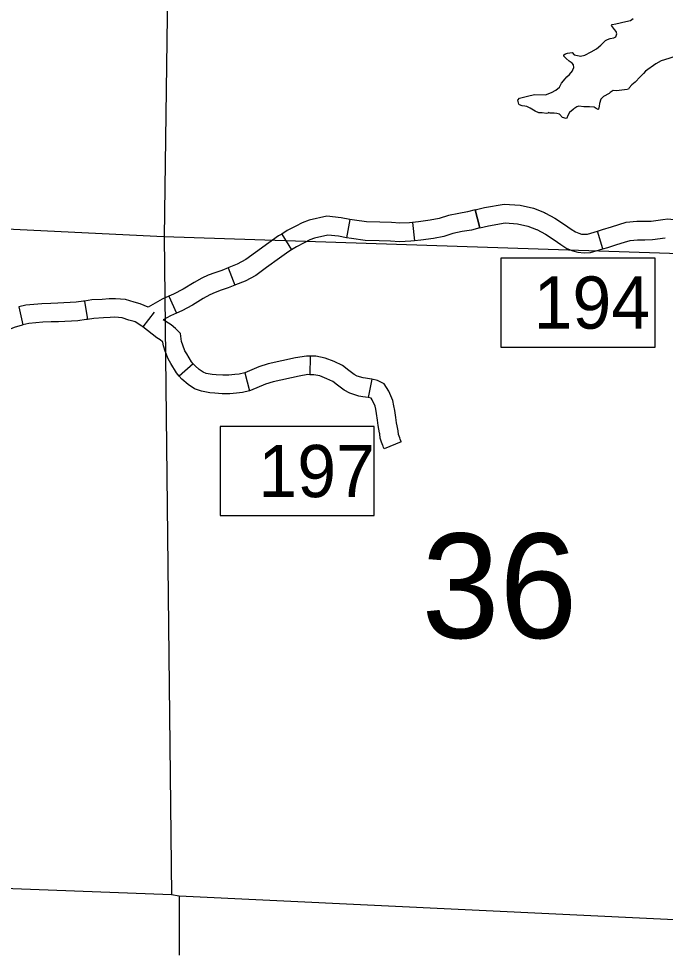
# Model space of a CAD drawing. Extents: x -492261 to -432772, y 1441225 to 1452922.
# Drawn here: x -463526 to -463376.9, y 1450874.7 to 1451090.8 of the extents above; entities that cross this region are included whole.
import ezdxf

# ---------------------------------------------------------------- set-up
doc = ezdxf.new("R2010")
doc.units = 0
doc.layers.add('Default', color=7, linetype='Continuous')

msp = doc.modelspace()

# ---------------------------------------------------------------- linework, layer by layer
at = {"layer": 'Default'}
for p, q in [((-463419.67, 1451042.53), (-463420.73, 1451046.69)), ((-463420.73, 1451046.69), (-463419.67, 1451042.53)), ((-463449.62, 1451044.5), (-463450.39, 1451040.28)), ((-463435.21, 1451043.81), (-463434.74, 1451039.55)), ((-463465.35, 1451041.12), (-463463.1, 1451037.47)), ((-463391.27, 1451037.7), (-463392.54, 1451041.79)), ((-463477.72, 1451033.31), (-463476.17, 1451029.31)), ((-463510.88, 1451025.65), (-463510.19, 1451021.42)), ((-463491.39, 1451026.79), (-463489.65, 1451022.87)), ((-463526.02, 1451024.35), (-463525.05, 1451020.18)), ((-463494.76, 1451023.07), (-463497.39, 1451019.69)), ((-463458.76, 1451012.95), (-463458.87, 1451008.67)), ((-463485.75, 1451011.15), (-463488.99, 1451008.35)), ((-463473.88, 1451009.12), (-463472.81, 1451004.97)), ((-463444.55, 1451007.63), (-463445.45, 1451003.44)), ((-463437.77, 1450993.16), (-463441.74, 1450991.55))]:
    msp.add_line(p, q, dxfattribs=at)
for points in [[(-463491.53, 1451108.34), (-463492.51, 1451040.46), (-463490.8, 1450888.59)], [(-463383.83, 1451076.16), (-463384.57, 1451075.58), (-463385.19, 1451074.88), (-463385.36, 1451074.59), (-463385.7, 1451074.48), (-463388.15, 1451074.21), (-463388.9, 1451074.26), (-463389.58, 1451073.8), (-463389.86, 1451073.56), (-463391.11, 1451072.86), (-463391.78, 1451072.28), (-463392.06, 1451071.25), (-463392.11, 1451070.62), (-463392.27, 1451069.99), (-463392.38, 1451069.87), (-463392.84, 1451070.09), (-463393.3, 1451070.43), (-463394.39, 1451070.48), (-463394.73, 1451070.47), (-463395.65, 1451070.46), (-463396.85, 1451070.62), (-463397.3, 1451070.5), (-463397.98, 1451070.03), (-463398.15, 1451069.91), (-463398.94, 1451069.16), (-463399.34, 1451068.52), (-463399.56, 1451067.84), (-463399.78, 1451067.78), (-463400.59, 1451068.05), (-463401.28, 1451068.79), (-463401.91, 1451068.95), (-463402.48, 1451069.06), (-463403.46, 1451069.04), (-463403.91, 1451069.15), (-463403.91, 1451069.04), (-463404.25, 1451068.92), (-463405.28, 1451069.08), (-463406.03, 1451069.13), (-463406.89, 1451069.51), (-463408.04, 1451070.19), (-463408.79, 1451070.58), (-463409.3, 1451070.63), (-463409.88, 1451070.73), (-463410.51, 1451070.96), (-463410.68, 1451071.12), (-463410.87, 1451072.04), (-463410.53, 1451072.5), (-463408.02, 1451073.1), (-463407, 1451073.34), (-463404.54, 1451073.26), (-463403.12, 1451073.79), (-463402.09, 1451074.32), (-463401.3, 1451075.02), (-463400.8, 1451075.94), (-463400.01, 1451076.92), (-463399.56, 1451077.39), (-463399, 1451077.96), (-463398.32, 1451078.83), (-463398.21, 1451079), (-463397.99, 1451079.58), (-463398.06, 1451080.15), (-463398.35, 1451080.55), (-463399.04, 1451081.05), (-463399.73, 1451081.62), (-463400.31, 1451082.18), (-463400.31, 1451082.52), (-463399.86, 1451082.76), (-463399.4, 1451082.88), (-463398.38, 1451083.01), (-463397.91, 1451082.5), (-463396.77, 1451082.28), (-463396.42, 1451082.17), (-463395.46, 1451082.41), (-463393.98, 1451083.18), (-463392.73, 1451083.88), (-463391.71, 1451084.75), (-463390.64, 1451085.79), (-463390.19, 1451086.03), (-463389.62, 1451086.26), (-463388.76, 1451086.39), (-463388.25, 1451086.68), (-463388.03, 1451087.31), (-463388.21, 1451087.88), (-463388.56, 1451088.33), (-463389.32, 1451089.24), (-463389.15, 1451089.53), (-463388.29, 1451089.65), (-463385.96, 1451090.2), (-463384.93, 1451090.38), (-463384.25, 1451090.85)], [(-463368.01, 1451076.36), (-463368.01, 1451076.02), (-463368.35, 1451075.84), (-463369.03, 1451075.77), (-463369.55, 1451075.88), (-463370.24, 1451076.39), (-463370.42, 1451076.84), (-463370.71, 1451077.81), (-463370.9, 1451079.01), (-463371.2, 1451080.38), (-463371.73, 1451081.12), (-463372.31, 1451081.74), (-463373.11, 1451082.13), (-463374.48, 1451082.22), (-463376.08, 1451081.63), (-463377.84, 1451081.09), (-463379.03, 1451080.39), (-463381.41, 1451078.76), (-463381.92, 1451078.18), (-463382.65, 1451077.43), (-463383.83, 1451076.16)], [(-463345.55, 1451035.65), (-463492.57, 1451040.51), (-463644.02, 1451047.89), (-463656.98, 1451048.34)], [(-463420.73, 1451046.69), (-463418.57, 1451047.23), (-463414.08, 1451048), (-463410.35, 1451047.77), (-463407.27, 1451047.08), (-463404.77, 1451046.07), (-463404.5, 1451045.93)], [(-463449.62, 1451044.5), (-463451.64, 1451044.87), (-463454.93, 1451045.24), (-463459.03, 1451044.31), (-463460.64, 1451043.69), (-463462.12, 1451042.94), (-463464.07, 1451041.91), (-463465.35, 1451041.12)], [(-463420.73, 1451046.69), (-463422.5, 1451046.24), (-463424.51, 1451045.89), (-463426.92, 1451045.39), (-463429.01, 1451044.75), (-463431.08, 1451044.37), (-463433.79, 1451043.96), (-463435.21, 1451043.81)], [(-463404.5, 1451045.93), (-463402.36, 1451044.79), (-463400.13, 1451043.36), (-463398.58, 1451042.27), (-463397.59, 1451041.63), (-463396.85, 1451041.34), (-463396.21, 1451041.14), (-463395.5, 1451041.07), (-463394.83, 1451041.11), (-463393.25, 1451041.57), (-463392.54, 1451041.79)], [(-463435.21, 1451043.81), (-463435.89, 1451043.73), (-463438.11, 1451043.66), (-463440.04, 1451043.76), (-463442.75, 1451043.86), (-463445.79, 1451043.95), (-463448.6, 1451044.31), (-463449.62, 1451044.5)], [(-463419.67, 1451042.53), (-463417.68, 1451043.04), (-463413.85, 1451043.69), (-463410.95, 1451043.51), (-463408.55, 1451042.98), (-463406.58, 1451042.18), (-463406.52, 1451042.15)], [(-463392.54, 1451041.79), (-463391.39, 1451042.15), (-463389.28, 1451042.79), (-463387.58, 1451043.31), (-463385.91, 1451043.84), (-463383.44, 1451044.12), (-463381.65, 1451044.08), (-463380.16, 1451044.14), (-463377.44, 1451044.49)], [(-463377.44, 1451044.49), (-463376.3, 1451044.64), (-463371.96, 1451044.17), (-463364.65, 1451043.13), (-463361.98, 1451042.87)], [(-463465.35, 1451041.12), (-463466.07, 1451040.68), (-463468.35, 1451039.07), (-463471.39, 1451036.86), (-463473.6, 1451035.22), (-463475.63, 1451034.14), (-463477.56, 1451033.37), (-463477.72, 1451033.31)], [(-463450.39, 1451040.28), (-463452.27, 1451040.63), (-463454.69, 1451040.9), (-463457.77, 1451040.2), (-463458.89, 1451039.77), (-463460.15, 1451039.13), (-463461.95, 1451038.18), (-463463.1, 1451037.47)], [(-463419.67, 1451042.53), (-463421.61, 1451042.04), (-463423.71, 1451041.68), (-463425.86, 1451041.23), (-463427.99, 1451040.58), (-463430.37, 1451040.14), (-463433.24, 1451039.71), (-463434.74, 1451039.55)], [(-463406.52, 1451042.15), (-463404.53, 1451041.09), (-463402.52, 1451039.8), (-463400.98, 1451038.73), (-463399.56, 1451037.79), (-463398.24, 1451037.29), (-463397.06, 1451036.92), (-463395.59, 1451036.78), (-463394.1, 1451036.86), (-463392.02, 1451037.46), (-463391.27, 1451037.7)], [(-463434.74, 1451039.55), (-463435.59, 1451039.45), (-463438.16, 1451039.37), (-463440.23, 1451039.48), (-463442.89, 1451039.58), (-463446.13, 1451039.67), (-463449.26, 1451040.08), (-463450.39, 1451040.28)], [(-463391.27, 1451037.7), (-463390.13, 1451038.05), (-463388.02, 1451038.69), (-463386.3, 1451039.22), (-463385.01, 1451039.63), (-463383.26, 1451039.83), (-463381.62, 1451039.79), (-463379.8, 1451039.86), (-463376.89, 1451040.24)], [(-463463.1, 1451037.47), (-463463.71, 1451037.1), (-463465.86, 1451035.59), (-463468.85, 1451033.41), (-463471.3, 1451031.59), (-463473.82, 1451030.24), (-463475.99, 1451029.38), (-463476.17, 1451029.31)], [(-463414.79, 1451015.05), (-463379.23, 1451015.05), (-463379.23, 1451035.6), (-463414.79, 1451035.6), (-463414.79, 1451015.05)], [(-463477.72, 1451033.31), (-463479.17, 1451032.75), (-463480.81, 1451032.17), (-463482.33, 1451031.61), (-463483.82, 1451030.91), (-463485.59, 1451029.98), (-463488.09, 1451028.43), (-463490.29, 1451027.28), (-463491.39, 1451026.79)], [(-463476.17, 1451029.31), (-463477.68, 1451028.73), (-463479.35, 1451028.14), (-463480.68, 1451027.65), (-463481.92, 1451027.07), (-463483.45, 1451026.26), (-463485.96, 1451024.7), (-463488.43, 1451023.42), (-463489.65, 1451022.87)], [(-463510.88, 1451025.65), (-463511.06, 1451025.62), (-463512.78, 1451025.39), (-463516.98, 1451025.14), (-463518.61, 1451025.13), (-463520.69, 1451025.06), (-463524.38, 1451024.73), (-463526.02, 1451024.35)], [(-463496.19, 1451024.24), (-463498, 1451025.03), (-463499.43, 1451025.4), (-463501.38, 1451026.01), (-463503.71, 1451026.2), (-463505.13, 1451026.19), (-463506.78, 1451026.06), (-463509.16, 1451025.93), (-463510.88, 1451025.65)], [(-463491.39, 1451026.79), (-463492.95, 1451026.1), (-463496.19, 1451024.24)], [(-463510.19, 1451021.42), (-463510.44, 1451021.38), (-463512.37, 1451021.12), (-463516.84, 1451020.86), (-463518.52, 1451020.85), (-463520.43, 1451020.78), (-463523.7, 1451020.49), (-463525.05, 1451020.18)], [(-463497.39, 1451019.69), (-463497.65, 1451019.89), (-463499.2, 1451020.88), (-463499.4, 1451020.97), (-463500.61, 1451021.27), (-463502.2, 1451021.78), (-463503.87, 1451021.91), (-463504.95, 1451021.9), (-463506.5, 1451021.78), (-463508.69, 1451021.66), (-463510.19, 1451021.42)], [(-463489.65, 1451022.87), (-463491.01, 1451022.27), (-463492.7, 1451021.3)], [(-463485.75, 1451011.15), (-463486.17, 1451011.63), (-463487.28, 1451013.47), (-463487.69, 1451014.14), (-463488.19, 1451015.52), (-463488.47, 1451016.33), (-463488.71, 1451018.17), (-463489.89, 1451019.33), (-463490.83, 1451020.19), (-463492.7, 1451021.3)], [(-463525.05, 1451020.18), (-463525.24, 1451020.13), (-463527.07, 1451019.54), (-463528.53, 1451018.96), (-463529.41, 1451018.53), (-463530.07, 1451017.97), (-463530.66, 1451017.24), (-463531.92, 1451015.56), (-463533.95, 1451013.13), (-463535.5, 1451011.61)], [(-463488.99, 1451008.35), (-463489.65, 1451009.1), (-463490.95, 1451011.25), (-463491.58, 1451012.29), (-463492.24, 1451014.1), (-463492.66, 1451015.35), (-463492.76, 1451016.15), (-463492.85, 1451016.23), (-463493.4, 1451016.73), (-463494.18, 1451017.2), (-463497.39, 1451019.69)], [(-463458.76, 1451012.95), (-463459.63, 1451012.98), (-463462.16, 1451012.58), (-463468.49, 1451011.19), (-463470.61, 1451010.48), (-463473.9, 1451009.12), (-463473.88, 1451009.12)], [(-463444.55, 1451007.63), (-463444.66, 1451007.66), (-463446.04, 1451007.83), (-463446.58, 1451007.91), (-463447.93, 1451008.35), (-463448.66, 1451008.75), (-463449.91, 1451009.67), (-463451.33, 1451010.77), (-463453.26, 1451011.68), (-463455.35, 1451012.52), (-463457.49, 1451012.92), (-463458.76, 1451012.95)], [(-463473.88, 1451009.12), (-463475.2, 1451008.78), (-463476.16, 1451008.68), (-463477.54, 1451008.57), (-463478.98, 1451008.56), (-463480.46, 1451008.65), (-463481.38, 1451008.75), (-463482.75, 1451008.98), (-463483.47, 1451009.26), (-463484.38, 1451009.86), (-463485.36, 1451010.7), (-463485.75, 1451011.15)], [(-463472.81, 1451004.97), (-463474.43, 1451004.56), (-463475.76, 1451004.41), (-463477.35, 1451004.28), (-463479.1, 1451004.27), (-463480.82, 1451004.38), (-463481.95, 1451004.5), (-463483.9, 1451004.83), (-463485.46, 1451005.44), (-463486.96, 1451006.43), (-463488.39, 1451007.64), (-463488.99, 1451008.35)], [(-463458.87, 1451008.67), (-463459.35, 1451008.68), (-463461.37, 1451008.36), (-463467.36, 1451007.05), (-463469.11, 1451006.47), (-463472.54, 1451005.04), (-463472.81, 1451004.97)], [(-463445.38, 1451003.43), (-463446.62, 1451003.58), (-463447.57, 1451003.72), (-463449.65, 1451004.4), (-463450.98, 1451005.13), (-463452.49, 1451006.25), (-463453.58, 1451007.09), (-463454.98, 1451007.75), (-463456.55, 1451008.38), (-463457.94, 1451008.64), (-463458.87, 1451008.67)], [(-463437.77, 1450993.16), (-463437.86, 1450993.39), (-463438.01, 1450993.81), (-463438.15, 1450994.1), (-463438.3, 1450994.47), (-463438.4, 1450994.83), (-463438.51, 1450995.73), (-463438.59, 1450996.11), (-463438.75, 1450996.86), (-463438.86, 1450997.58), (-463439.04, 1450998.78), (-463439.28, 1451000.41), (-463439.46, 1451001.47), (-463439.69, 1451002.7), (-463440.66, 1451004.9), (-463441.69, 1451006.57), (-463443.28, 1451007.36), (-463444.55, 1451007.63)], [(-463441.74, 1450991.55), (-463441.88, 1450991.89), (-463441.97, 1450992.15), (-463442.06, 1450992.32), (-463442.37, 1450993.09), (-463442.62, 1450993.99), (-463442.74, 1450995.04), (-463442.78, 1450995.22), (-463442.97, 1450996.08), (-463443.1, 1450996.96), (-463443.28, 1450998.16), (-463443.51, 1450999.73), (-463443.68, 1451000.73), (-463443.81, 1451001.44), (-463444.46, 1451002.9), (-463444.69, 1451003.27), (-463444.7, 1451003.28), (-463445.45, 1451003.44)], [(-463479.58, 1450976.15), (-463444.01, 1450976.15), (-463444.01, 1450996.7), (-463479.58, 1450996.7), (-463479.58, 1450976.15)], [(-463355.45, 1450881.93), (-463489.03, 1450888.27), (-463490.8, 1450888.59), (-463639.38, 1450894.24), (-463643.2, 1450894.13), (-463774.52, 1450897.57)], [(-463489.03, 1450888.27), (-463489.05, 1450874.66)]]:
    msp.add_lwpolyline(points, dxfattribs=at)
for points in [[(-463414.79, 1451015.05), (-463379.23, 1451015.05), (-463379.23, 1451035.6), (-463414.79, 1451035.6)], [(-463479.58, 1450976.15), (-463444.01, 1450976.15), (-463444.01, 1450996.7), (-463479.58, 1450996.7)]]:
    msp.add_lwpolyline(points, close=True, dxfattribs=at)

# ---------------------------------------------------------------- texts
for s, height, p in [('194', 12.057, (-463407.27, 1451019.29)), ('197', 12.057, (-463470.75, 1450980.4)), ('36', 24.137, (-463433.09, 1450947.88))]:
    msp.add_text(s, height=height, dxfattribs=at).set_placement(p)

doc.saveas('drawing.dxf')
